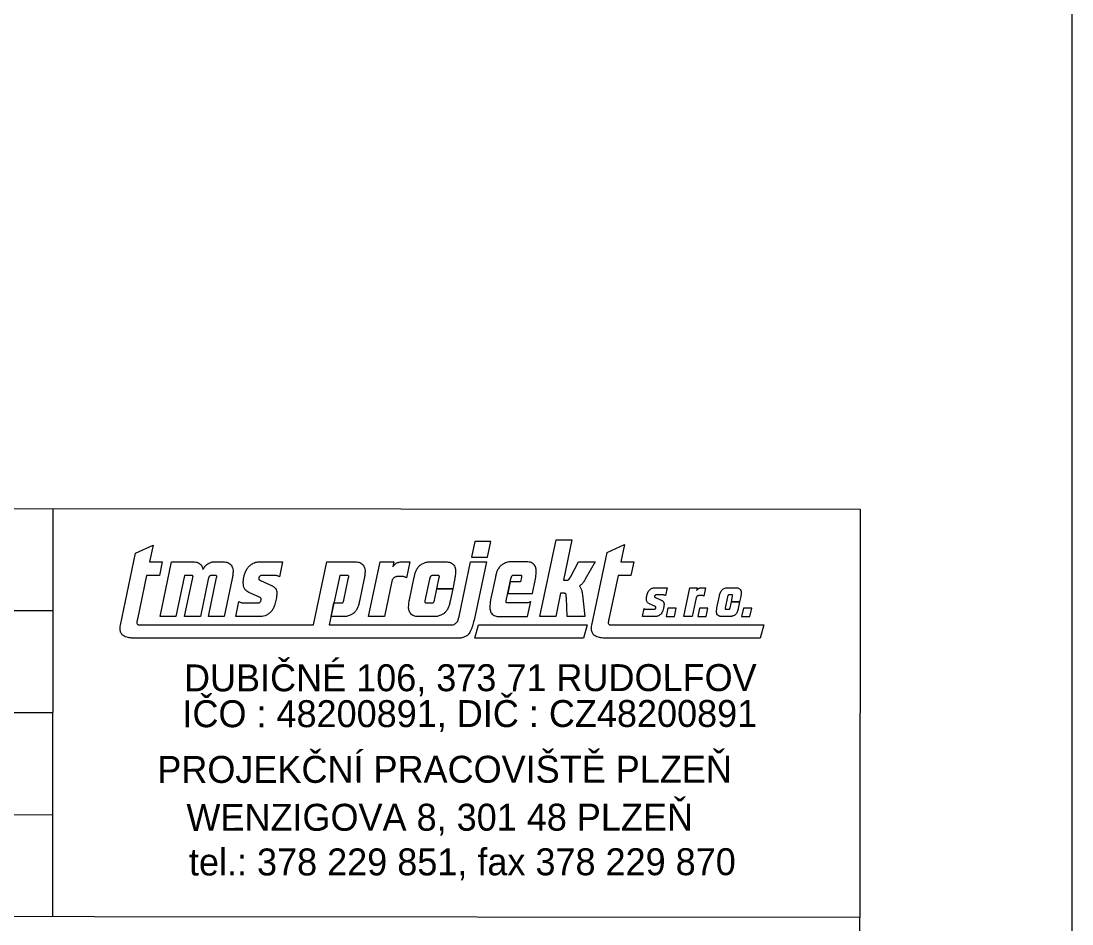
# Model space of a CAD drawing. Extents: x -712879 to -712656, y -1106692 to -1106395.
# Drawn here: x -712742.8 to -712668.6, y -1106637.9 to -1106574.3 of the extents above; entities that cross this region are included whole.
import ezdxf

# ---------------------------------------------------------------- set-up
doc = ezdxf.new("R2010")
doc.units = 0
doc.layers.add('Implicitní', color=7, linetype='Continuous')
doc.layers.add('Vrstva 63', color=7, linetype='Continuous')

msp = doc.modelspace()

# ---------------------------------------------------------------- linework, layer by layer
at = {"layer": 'Implicitní'}
for p, q in [((-712740.521, -1106608.636), (-712740.542, -1106637.436)), ((-712710.731, -1106610.956), (-712710.967, -1106612.074)), ((-712709.618, -1106610.956), (-712710.731, -1106610.956)), ((-712709.854, -1106612.074), (-712709.618, -1106610.956)), ((-712706.146, -1106616.265), (-712705.004, -1106610.846)), ((-712705.004, -1106610.846), (-712703.891, -1106610.846)), ((-712703.891, -1106610.846), (-712704.489, -1106613.684)), ((-712735.743, -1106616.859), (-712734.673, -1106611.779)), ((-712734.674, -1106611.779), (-712733.442, -1106611.218)), ((-712733.442, -1106611.218), (-712733.691, -1106612.402)), ((-712702.483, -1106616.859), (-712701.403, -1106611.73)), ((-712701.403, -1106611.73), (-712700.172, -1106611.169)), ((-712700.172, -1106611.169), (-712700.431, -1106612.402)), ((-712733.691, -1106612.402), (-712732.789, -1106612.402)), ((-712732.789, -1106612.402), (-712732.992, -1106613.367)), ((-712732.942, -1106616.265), (-712732.128, -1106612.402)), ((-712732.128, -1106612.402), (-712730.697, -1106612.402)), ((-712729.195, -1106612.402), (-712728.581, -1106612.402)), ((-712725.923, -1106612.402), (-712724.304, -1106612.402)), ((-712724.304, -1106612.402), (-712724.526, -1106613.455)), ((-712722.119, -1106616.854), (-712721.181, -1106612.402)), ((-712721.181, -1106612.402), (-712719.268, -1106612.402)), ((-712718.234, -1106616.265), (-712717.421, -1106612.402)), ((-712717.421, -1106612.402), (-712716.45, -1106612.402)), ((-712716.45, -1106612.402), (-712716.526, -1106612.764)), ((-712715.933, -1106612.402), (-712715.332, -1106612.402)), ((-712715.332, -1106612.402), (-712715.568, -1106613.522)), ((-712713.887, -1106612.402), (-712712.876, -1106612.402)), ((-712711.848, -1106616.257), (-712711.036, -1106612.402)), ((-712711.036, -1106612.402), (-712709.922, -1106612.402)), ((-712710.967, -1106612.074), (-712709.854, -1106612.074)), ((-712709.922, -1106612.402), (-712710.791, -1106616.526)), ((-712707.183, -1106612.402), (-712708.157, -1106612.402)), ((-712703.971, -1106613.445), (-712703.428, -1106612.402)), ((-712703.428, -1106612.402), (-712702.248, -1106612.402)), ((-712702.248, -1106612.402), (-712702.95, -1106613.632)), ((-712700.431, -1106612.402), (-712699.529, -1106612.402)), ((-712699.529, -1106612.402), (-712699.732, -1106613.367)), ((-712733.895, -1106613.367), (-712734.544, -1106616.451)), ((-712732.992, -1106613.367), (-712733.895, -1106613.367)), ((-712731.218, -1106613.367), (-712731.828, -1106616.265)), ((-712730.723, -1106613.367), (-712731.218, -1106613.367)), ((-712731.212, -1106616.265), (-712730.632, -1106613.51)), ((-712729.542, -1106613.622), (-712730.099, -1106616.265)), ((-712729.533, -1106616.265), (-712728.953, -1106613.512)), ((-712729.045, -1106613.367), (-712729.341, -1106613.367)), ((-712727.855, -1106613.581), (-712728.42, -1106616.265)), ((-712725.865, -1106613.723), (-712725.077, -1106614.076)), ((-712724.813, -1106613.367), (-712725.764, -1106613.367)), ((-712720.272, -1106613.367), (-712721.006, -1106616.854)), ((-712719.733, -1106613.367), (-712720.272, -1106613.367)), ((-712719.977, -1106615.098), (-712719.642, -1106613.509)), ((-712718.545, -1106613.584), (-712718.881, -1106615.181)), ((-712716.593, -1106613.757), (-712717.121, -1106616.265)), ((-712715.855, -1106613.435), (-712716.149, -1106613.435)), ((-712715.353, -1106615.079), (-712715.017, -1106613.483)), ((-712713.933, -1106613.622), (-712714.254, -1106615.149)), ((-712713.34, -1106613.367), (-712713.733, -1106613.367)), ((-712713.417, -1106614.304), (-712713.249, -1106613.509)), ((-712712.148, -1106613.587), (-712712.299, -1106614.304)), ((-712709.286, -1106613.485), (-712709.621, -1106615.077)), ((-712708.523, -1106615.148), (-712708.195, -1106613.588)), ((-712708.239, -1106613.799), (-712708.413, -1106614.622)), ((-712707.514, -1106613.799), (-712708.239, -1106613.799)), ((-712707.993, -1106613.331), (-712707.537, -1106613.331)), ((-712707.446, -1106613.474), (-712707.514, -1106613.799)), ((-712706.675, -1106614.622), (-712706.457, -1106613.588)), ((-712704.489, -1106613.684), (-712704.247, -1106613.684)), ((-712700.635, -1106613.367), (-712701.284, -1106616.451)), ((-712699.732, -1106613.367), (-712700.635, -1106613.367)), ((-712725.983, -1106614.867), (-712726.675, -1106614.558)), ((-712713.584, -1106615.098), (-712713.417, -1106614.304)), ((-712713.417, -1106614.304), (-712712.299, -1106614.304)), ((-712712.299, -1106614.304), (-712713.417, -1106614.304)), ((-712712.299, -1106614.304), (-712712.484, -1106615.182)), ((-712708.413, -1106614.622), (-712706.675, -1106614.622)), ((-712704.685, -1106614.615), (-712705.032, -1106616.265)), ((-712704.49, -1106614.615), (-712704.685, -1106614.615)), ((-712703.15, -1106614.717), (-712702.966, -1106616.265)), ((-712698.026, -1106614.229), (-712697.176, -1106614.229)), ((-712697.443, -1106614.736), (-712697.942, -1106614.736)), ((-712697.176, -1106614.229), (-712697.292, -1106614.782)), ((-712695.985, -1106616.258), (-712695.557, -1106614.229)), ((-712695.557, -1106614.229), (-712695.048, -1106614.229)), ((-712695.048, -1106614.229), (-712695.088, -1106614.42)), ((-712694.777, -1106614.229), (-712694.461, -1106614.229)), ((-712694.461, -1106614.229), (-712694.585, -1106614.817)), ((-712692.886, -1106614.229), (-712692.355, -1106614.229)), ((-712692.599, -1106614.736), (-712692.805, -1106614.736)), ((-712727.607, -1106616.265), (-712727.383, -1106615.204)), ((-712727.094, -1106615.291), (-712726.034, -1106615.291)), ((-712720.882, -1106616.265), (-712720.677, -1106615.291)), ((-712720.677, -1106615.291), (-712720.148, -1106615.291)), ((-712714.163, -1106615.291), (-712713.756, -1106615.291)), ((-712707.134, -1106615.291), (-712708.432, -1106615.291)), ((-712707.021, -1106616.265), (-712706.797, -1106615.202)), ((-712704.226, -1106616.265), (-712704.274, -1106614.939)), ((-712698.057, -1106615.524), (-712698.421, -1106615.361)), ((-712697.996, -1106614.923), (-712697.582, -1106615.108)), ((-712695.123, -1106614.941), (-712695.4, -1106616.258)), ((-712694.735, -1106614.772), (-712694.89, -1106614.772)), ((-712693.656, -1106615.635), (-712693.479, -1106614.797)), ((-712692.91, -1106614.87), (-712693.079, -1106615.671)), ((-712692.727, -1106615.645), (-712692.639, -1106615.228)), ((-712692.639, -1106615.228), (-712692.551, -1106614.811)), ((-712692.639, -1106615.228), (-712692.052, -1106615.228)), ((-712692.052, -1106615.228), (-712692.639, -1106615.228)), ((-712692.052, -1106615.228), (-712692.149, -1106615.689)), ((-712691.973, -1106614.851), (-712692.052, -1106615.228)), ((-712845.565, -1106615.757), (-712740.526, -1106615.835)), ((-712698.91, -1106616.258), (-712698.793, -1106615.7)), ((-712698.641, -1106615.746), (-712698.084, -1106615.746)), ((-712697.114, -1106615.67), (-712697.238, -1106616.258)), ((-712696.529, -1106615.67), (-712697.114, -1106615.67)), ((-712696.653, -1106616.258), (-712696.529, -1106615.67)), ((-712694.878, -1106615.67), (-712695.002, -1106616.258)), ((-712694.294, -1106615.67), (-712694.878, -1106615.67)), ((-712694.417, -1106616.258), (-712694.294, -1106615.67)), ((-712693.031, -1106615.746), (-712692.817, -1106615.746)), ((-712691.789, -1106615.67), (-712691.913, -1106616.258)), ((-712691.205, -1106615.67), (-712691.789, -1106615.67)), ((-712691.328, -1106616.258), (-712691.205, -1106615.67)), ((-712734.359, -1106616.854), (-712722.119, -1106616.854)), ((-712731.828, -1106616.265), (-712732.942, -1106616.265)), ((-712730.099, -1106616.265), (-712731.212, -1106616.265)), ((-712728.42, -1106616.265), (-712729.533, -1106616.265)), ((-712725.97, -1106616.265), (-712727.607, -1106616.265)), ((-712721.006, -1106616.854), (-712712.459, -1106616.854)), ((-712720.012, -1106616.265), (-712720.882, -1106616.265)), ((-712717.121, -1106616.265), (-712718.234, -1106616.265)), ((-712713.614, -1106616.265), (-712714.628, -1106616.265)), ((-712710.738, -1106617.782), (-712710.481, -1106616.854)), ((-712710.481, -1106616.854), (-712702.82, -1106616.854)), ((-712708.898, -1106616.265), (-712707.021, -1106616.265)), ((-712705.032, -1106616.265), (-712706.146, -1106616.265)), ((-712702.966, -1106616.265), (-712704.226, -1106616.265)), ((-712702.82, -1106616.854), (-712703.076, -1106617.782)), ((-712701.099, -1106616.854), (-712690.345, -1106616.854)), ((-712698.051, -1106616.258), (-712698.91, -1106616.258)), ((-712697.238, -1106616.258), (-712696.653, -1106616.258)), ((-712695.4, -1106616.258), (-712695.985, -1106616.258)), ((-712695.002, -1106616.258), (-712694.417, -1106616.258)), ((-712692.743, -1106616.258), (-712693.275, -1106616.258)), ((-712691.913, -1106616.258), (-712691.328, -1106616.258)), ((-712690.345, -1106616.854), (-712690.602, -1106617.782)), ((-712711.906, -1106617.782), (-712734.869, -1106617.782)), ((-712703.076, -1106617.782), (-712710.738, -1106617.782)), ((-712690.602, -1106617.782), (-712701.609, -1106617.782)), ((-712845.571, -1106622.957), (-712740.532, -1106623.035)), ((-712845.576, -1106630.157), (-712740.537, -1106630.235))]:
    msp.add_line(p, q, dxfattribs=at)
for points in [[(-712845.56, -1106608.557), (-712683.555, -1106608.677), (-712683.576, -1106637.478), (-712845.581, -1106637.358)], [(-712845.585, -1106644.557), (-712683.582, -1106644.677), (-712683.576, -1106637.478), (-712845.579, -1106637.358)]]:
    msp.add_lwpolyline(points, close=True, dxfattribs=at)
for points in [[(-712730.697, -1106612.401), (-712730.605, -1106612.402), (-712730.429, -1106612.415), (-712730.286, -1106612.447), (-712730.142, -1106612.53), (-712729.968, -1106612.761), (-712729.938, -1106612.872), (-712729.925, -1106612.921), (-712729.919, -1106612.949)], [(-712729.919, -1106612.949), (-712729.815, -1106612.775), (-712729.707, -1106612.647), (-712729.571, -1106612.536), (-712729.48, -1106612.483), (-712729.373, -1106612.44), (-712729.29, -1106612.419), (-712729.195, -1106612.402)], [(-712728.581, -1106612.401), (-712728.489, -1106612.402), (-712728.313, -1106612.415), (-712728.169, -1106612.447), (-712728.026, -1106612.53), (-712727.852, -1106612.761), (-712727.822, -1106612.872), (-712727.809, -1106612.921), (-712727.814, -1106613.276), (-712727.831, -1106613.435), (-712727.855, -1106613.581)], [(-712726.675, -1106614.558), (-712726.819, -1106614.464), (-712726.93, -1106614.369), (-712727.031, -1106614.195), (-712727.068, -1106613.991), (-712727.072, -1106613.793), (-712727.037, -1106613.508), (-712726.985, -1106613.296), (-712726.886, -1106613.037), (-712726.758, -1106612.815), (-712726.593, -1106612.649), (-712726.376, -1106612.499), (-712726.207, -1106612.433), (-712726.045, -1106612.404), (-712725.923, -1106612.402)], [(-712719.268, -1106612.401), (-712719.176, -1106612.402), (-712718.999, -1106612.415), (-712718.856, -1106612.447), (-712718.712, -1106612.53), (-712718.538, -1106612.761), (-712718.508, -1106612.872), (-712718.496, -1106612.921), (-712718.5, -1106613.276), (-712718.518, -1106613.435), (-712718.545, -1106613.584)], [(-712716.526, -1106612.764), (-712716.455, -1106612.667), (-712716.399, -1106612.603), (-712716.313, -1106612.528), (-712716.238, -1106612.482), (-712716.133, -1106612.436), (-712716.043, -1106612.413), (-712715.933, -1106612.402)], [(-712715.017, -1106613.483), (-712714.966, -1106613.256), (-712714.885, -1106613.026), (-712714.758, -1106612.809), (-712714.631, -1106612.666), (-712714.451, -1106612.547), (-712714.299, -1106612.473), (-712714.168, -1106612.431), (-712714.048, -1106612.406), (-712713.887, -1106612.402)], [(-712712.876, -1106612.401), (-712712.784, -1106612.402), (-712712.607, -1106612.415), (-712712.464, -1106612.447), (-712712.32, -1106612.53), (-712712.146, -1106612.761), (-712712.116, -1106612.872), (-712712.104, -1106612.921), (-712712.108, -1106613.276), (-712712.126, -1106613.435), (-712712.148, -1106613.587)], [(-712708.157, -1106612.402), (-712708.317, -1106612.406), (-712708.438, -1106612.431), (-712708.569, -1106612.473), (-712708.721, -1106612.547), (-712708.901, -1106612.666), (-712709.028, -1106612.809), (-712709.154, -1106613.026), (-712709.236, -1106613.256), (-712709.286, -1106613.485)], [(-712706.457, -1106613.588), (-712706.433, -1106613.435), (-712706.416, -1106613.276), (-712706.411, -1106612.921), (-712706.424, -1106612.872), (-712706.454, -1106612.761), (-712706.628, -1106612.53), (-712706.771, -1106612.447), (-712706.915, -1106612.415), (-712707.091, -1106612.402), (-712707.183, -1106612.401)], [(-712730.632, -1106613.51), (-712730.626, -1106613.476), (-712730.621, -1106613.438), (-712730.627, -1106613.403), (-712730.645, -1106613.38), (-712730.678, -1106613.369), (-712730.723, -1106613.367)], [(-712729.341, -1106613.367), (-712729.37, -1106613.369), (-712729.403, -1106613.377), (-712729.437, -1106613.398), (-712729.48, -1106613.444), (-712729.503, -1106613.491), (-712729.542, -1106613.622)], [(-712728.953, -1106613.512), (-712728.947, -1106613.476), (-712728.942, -1106613.438), (-712728.949, -1106613.403), (-712728.967, -1106613.38), (-712729, -1106613.369), (-712729.045, -1106613.367)], [(-712725.764, -1106613.367), (-712725.84, -1106613.375), (-712725.881, -1106613.395), (-712725.926, -1106613.431), (-712725.957, -1106613.485), (-712725.975, -1106613.548), (-712725.977, -1106613.615), (-712725.958, -1106613.661), (-712725.914, -1106613.693), (-712725.865, -1106613.723)], [(-712724.526, -1106613.455), (-712724.589, -1106613.419), (-712724.654, -1106613.391), (-712724.693, -1106613.379), (-712724.763, -1106613.369), (-712724.813, -1106613.367)], [(-712719.642, -1106613.509), (-712719.635, -1106613.476), (-712719.63, -1106613.438), (-712719.637, -1106613.403), (-712719.655, -1106613.38), (-712719.688, -1106613.369), (-712719.733, -1106613.367)], [(-712716.149, -1106613.435), (-712716.22, -1106613.441), (-712716.289, -1106613.454), (-712716.372, -1106613.487), (-712716.444, -1106613.527), (-712716.499, -1106613.577), (-712716.56, -1106613.662), (-712716.593, -1106613.757)], [(-712715.568, -1106613.522), (-712715.632, -1106613.486), (-712715.697, -1106613.459), (-712715.736, -1106613.447), (-712715.788, -1106613.438), (-712715.855, -1106613.435)], [(-712713.733, -1106613.367), (-712713.762, -1106613.369), (-712713.795, -1106613.377), (-712713.829, -1106613.398), (-712713.872, -1106613.444), (-712713.895, -1106613.491), (-712713.934, -1106613.621)], [(-712713.249, -1106613.509), (-712713.243, -1106613.476), (-712713.238, -1106613.438), (-712713.244, -1106613.403), (-712713.262, -1106613.38), (-712713.296, -1106613.369), (-712713.34, -1106613.367)], [(-712708.195, -1106613.588), (-712708.155, -1106613.454), (-712708.132, -1106613.408), (-712708.089, -1106613.361), (-712708.055, -1106613.34), (-712708.021, -1106613.332), (-712707.993, -1106613.331)], [(-712707.537, -1106613.331), (-712707.492, -1106613.333), (-712707.459, -1106613.343), (-712707.441, -1106613.366), (-712707.434, -1106613.401), (-712707.439, -1106613.44), (-712707.446, -1106613.474)], [(-712704.247, -1106613.684), (-712704.177, -1106613.682), (-712704.15, -1106613.673), (-712704.111, -1106613.647), (-712704.079, -1106613.611), (-712703.986, -1106613.475), (-712703.971, -1106613.445)], [(-712702.95, -1106613.632), (-712703.04, -1106613.79), (-712703.112, -1106613.89), (-712703.187, -1106613.969), (-712703.252, -1106614.029), (-712703.356, -1106614.107)], [(-712725.077, -1106614.076), (-712725.024, -1106614.101), (-712724.919, -1106614.171), (-712724.84, -1106614.241), (-712724.764, -1106614.34), (-712724.729, -1106614.427), (-712724.707, -1106614.662), (-712724.739, -1106614.927), (-712724.824, -1106615.321), (-712724.889, -1106615.529), (-712725.006, -1106615.771), (-712725.184, -1106615.982), (-712725.355, -1106616.113), (-712725.539, -1106616.204), (-712725.743, -1106616.254), (-712725.97, -1106616.265)], [(-712704.274, -1106614.939), (-712704.285, -1106614.791), (-712704.299, -1106614.688), (-712704.33, -1106614.651), (-712704.374, -1106614.628), (-712704.412, -1106614.618), (-712704.49, -1106614.615)], [(-712703.356, -1106614.107), (-712703.306, -1106614.188), (-712703.259, -1106614.263), (-712703.225, -1106614.33), (-712703.194, -1106614.433), (-712703.167, -1106614.572), (-712703.15, -1106614.717)], [(-712698.421, -1106615.361), (-712698.497, -1106615.312), (-712698.555, -1106615.262), (-712698.608, -1106615.171), (-712698.627, -1106615.064), (-712698.63, -1106614.96), (-712698.611, -1106614.81), (-712698.584, -1106614.699), (-712698.532, -1106614.563), (-712698.464, -1106614.446), (-712698.378, -1106614.359), (-712698.264, -1106614.28), (-712698.175, -1106614.246), (-712698.09, -1106614.23), (-712698.026, -1106614.229)], [(-712697.942, -1106614.736), (-712697.982, -1106614.74), (-712698.004, -1106614.751), (-712698.028, -1106614.77), (-712698.044, -1106614.798), (-712698.054, -1106614.831), (-712698.055, -1106614.866), (-712698.044, -1106614.89), (-712698.021, -1106614.907), (-712697.996, -1106614.923)], [(-712697.292, -1106614.782), (-712697.326, -1106614.763), (-712697.36, -1106614.749), (-712697.381, -1106614.742), (-712697.417, -1106614.737), (-712697.443, -1106614.736)], [(-712695.088, -1106614.42), (-712695.051, -1106614.368), (-712695.021, -1106614.335), (-712694.976, -1106614.296), (-712694.936, -1106614.271), (-712694.881, -1106614.247), (-712694.834, -1106614.235), (-712694.777, -1106614.229)], [(-712693.479, -1106614.797), (-712693.452, -1106614.678), (-712693.41, -1106614.557), (-712693.343, -1106614.443), (-712693.277, -1106614.368), (-712693.182, -1106614.306), (-712693.102, -1106614.267), (-712693.034, -1106614.244), (-712692.97, -1106614.231), (-712692.886, -1106614.229)], [(-712692.805, -1106614.736), (-712692.82, -1106614.737), (-712692.838, -1106614.741), (-712692.855, -1106614.752), (-712692.878, -1106614.777), (-712692.89, -1106614.801), (-712692.911, -1106614.87)], [(-712692.551, -1106614.811), (-712692.548, -1106614.793), (-712692.545, -1106614.773), (-712692.549, -1106614.755), (-712692.558, -1106614.743), (-712692.576, -1106614.737), (-712692.599, -1106614.736)], [(-712692.355, -1106614.229), (-712692.307, -1106614.23), (-712692.214, -1106614.236), (-712692.139, -1106614.253), (-712692.064, -1106614.297), (-712691.972, -1106614.418), (-712691.956, -1106614.476), (-712691.95, -1106614.502), (-712691.952, -1106614.688), (-712691.961, -1106614.772), (-712691.973, -1106614.851)], [(-712727.383, -1106615.204), (-712727.32, -1106615.24), (-712727.255, -1106615.268), (-712727.215, -1106615.279), (-712727.146, -1106615.29), (-712727.094, -1106615.291)], [(-712726.034, -1106615.291), (-712725.96, -1106615.288), (-712725.916, -1106615.262), (-712725.862, -1106615.203), (-712725.832, -1106615.129), (-712725.82, -1106615.036), (-712725.832, -1106614.979), (-712725.861, -1106614.94), (-712725.926, -1106614.901), (-712725.983, -1106614.867)], [(-712720.148, -1106615.291), (-712720.081, -1106615.289), (-712720.035, -1106615.263), (-712720.009, -1106615.208), (-712719.994, -1106615.16), (-712719.977, -1106615.098)], [(-712718.881, -1106615.181), (-712718.933, -1106615.411), (-712719.014, -1106615.64), (-712719.141, -1106615.858), (-712719.267, -1106616.001), (-712719.448, -1106616.119), (-712719.6, -1106616.194), (-712719.731, -1106616.236), (-712719.851, -1106616.261), (-712720.012, -1106616.265)], [(-712714.628, -1106616.265), (-712714.72, -1106616.264), (-712714.896, -1106616.251), (-712715.04, -1106616.22), (-712715.183, -1106616.137), (-712715.357, -1106615.906), (-712715.387, -1106615.794), (-712715.4, -1106615.746), (-712715.395, -1106615.391), (-712715.378, -1106615.232), (-712715.353, -1106615.079)], [(-712714.254, -1106615.149), (-712714.261, -1106615.183), (-712714.266, -1106615.221), (-712714.259, -1106615.256), (-712714.241, -1106615.279), (-712714.208, -1106615.289), (-712714.163, -1106615.291)], [(-712713.756, -1106615.291), (-712713.688, -1106615.289), (-712713.643, -1106615.263), (-712713.616, -1106615.208), (-712713.602, -1106615.16), (-712713.584, -1106615.098)], [(-712712.484, -1106615.182), (-712712.536, -1106615.411), (-712712.617, -1106615.64), (-712712.743, -1106615.858), (-712712.87, -1106616.001), (-712713.05, -1106616.119), (-712713.203, -1106616.194), (-712713.333, -1106616.236), (-712713.454, -1106616.261), (-712713.614, -1106616.265)], [(-712709.621, -1106615.077), (-712709.647, -1106615.232), (-712709.665, -1106615.391), (-712709.67, -1106615.746), (-712709.657, -1106615.794), (-712709.627, -1106615.906), (-712709.453, -1106616.137), (-712709.31, -1106616.22), (-712709.166, -1106616.251), (-712708.99, -1106616.264), (-712708.898, -1106616.265)], [(-712708.432, -1106615.291), (-712708.477, -1106615.289), (-712708.51, -1106615.279), (-712708.528, -1106615.256), (-712708.535, -1106615.221), (-712708.53, -1106615.183), (-712708.523, -1106615.148)], [(-712706.798, -1106615.202), (-712706.851, -1106615.233), (-712706.922, -1106615.268), (-712707.023, -1106615.291), (-712707.134, -1106615.291)], [(-712697.582, -1106615.108), (-712697.554, -1106615.121), (-712697.499, -1106615.158), (-712697.457, -1106615.195), (-712697.417, -1106615.247), (-712697.399, -1106615.292), (-712697.388, -1106615.416), (-712697.405, -1106615.555), (-712697.449, -1106615.762), (-712697.483, -1106615.871), (-712697.545, -1106615.998), (-712697.638, -1106616.109), (-712697.728, -1106616.178), (-712697.824, -1106616.225), (-712697.931, -1106616.251), (-712698.051, -1106616.258)], [(-712694.89, -1106614.772), (-712694.927, -1106614.775), (-712694.963, -1106614.782), (-712695.007, -1106614.799), (-712695.044, -1106614.82), (-712695.074, -1106614.846), (-712695.106, -1106614.891), (-712695.123, -1106614.941)], [(-712694.585, -1106614.817), (-712694.618, -1106614.799), (-712694.652, -1106614.784), (-712694.673, -1106614.778), (-712694.7, -1106614.774), (-712694.735, -1106614.772)], [(-712698.793, -1106615.7), (-712698.759, -1106615.719), (-712698.725, -1106615.734), (-712698.705, -1106615.74), (-712698.668, -1106615.745), (-712698.641, -1106615.746)], [(-712698.084, -1106615.746), (-712698.045, -1106615.744), (-712698.022, -1106615.731), (-712697.994, -1106615.7), (-712697.978, -1106615.661), (-712697.972, -1106615.612), (-712697.978, -1106615.582), (-712697.993, -1106615.562), (-712698.028, -1106615.541), (-712698.057, -1106615.524)], [(-712693.275, -1106616.258), (-712693.323, -1106616.257), (-712693.416, -1106616.25), (-712693.491, -1106616.234), (-712693.567, -1106616.19), (-712693.658, -1106616.069), (-712693.674, -1106616.01), (-712693.68, -1106615.985), (-712693.678, -1106615.798), (-712693.669, -1106615.715), (-712693.656, -1106615.635)], [(-712693.079, -1106615.671), (-712693.082, -1106615.689), (-712693.085, -1106615.709), (-712693.081, -1106615.728), (-712693.072, -1106615.74), (-712693.054, -1106615.745), (-712693.031, -1106615.746)], [(-712692.817, -1106615.746), (-712692.782, -1106615.745), (-712692.758, -1106615.731), (-712692.744, -1106615.703), (-712692.736, -1106615.677), (-712692.727, -1106615.645)], [(-712692.149, -1106615.689), (-712692.177, -1106615.809), (-712692.219, -1106615.929), (-712692.286, -1106616.044), (-712692.352, -1106616.119), (-712692.447, -1106616.181), (-712692.527, -1106616.22), (-712692.595, -1106616.242), (-712692.659, -1106616.255), (-712692.743, -1106616.258)], [(-712734.869, -1106617.782), (-712735.203, -1106617.742), (-712735.387, -1106617.686), (-712735.543, -1106617.605), (-712735.678, -1106617.465), (-712735.757, -1106617.237), (-712735.767, -1106617.074), (-712735.743, -1106616.859)], [(-712734.544, -1106616.451), (-712734.567, -1106616.56), (-712734.581, -1106616.668), (-712734.571, -1106616.766), (-712734.519, -1106616.826), (-712734.448, -1106616.847), (-712734.359, -1106616.854)], [(-712712.459, -1106616.854), (-712712.338, -1106616.85), (-712712.202, -1106616.813), (-712712.1, -1106616.751), (-712712.004, -1106616.665), (-712711.909, -1106616.483), (-712711.879, -1106616.377), (-712711.848, -1106616.257)], [(-712710.791, -1106616.526), (-712710.909, -1106616.932), (-712710.98, -1106617.136), (-712711.059, -1106617.305), (-712711.144, -1106617.451), (-712711.304, -1106617.613), (-712711.524, -1106617.72), (-712711.74, -1106617.778), (-712711.906, -1106617.782)], [(-712701.609, -1106617.782), (-712701.943, -1106617.742), (-712702.127, -1106617.686), (-712702.283, -1106617.605), (-712702.418, -1106617.465), (-712702.497, -1106617.237), (-712702.507, -1106617.074), (-712702.483, -1106616.859)], [(-712701.284, -1106616.451), (-712701.307, -1106616.56), (-712701.321, -1106616.668), (-712701.311, -1106616.766), (-712701.259, -1106616.826), (-712701.188, -1106616.847), (-712701.099, -1106616.854)]]:
    msp.add_spline(points, degree=3, dxfattribs=at)
at = {"layer": 'Vrstva 63'}
msp.add_lwpolyline([(-712878.605, -1106394.843), (-712668.605, -1106394.843), (-712668.605, -1106691.843), (-712878.605, -1106691.843)], close=True, dxfattribs=at)

# ---------------------------------------------------------------- texts
at = {"layer": 'Implicitní'}
for s, p in [('DUBIČNÉ 106, 373 71 RUDOLFOV', (-712731.256, -1106621.537)), ('IČO : 48200891, DIČ : CZ48200891', (-712731.367, -1106624.067)), ('PROJEKČNÍ PRACOVIŠTĚ PLZEŇ', (-712733.138, -1106627.996)), ('WENZIGOVA 8, 301 48 PLZEŇ', (-712731.086, -1106631.376)), ('tel.: 378 229 851, fax 378 229 870', (-712730.908, -1106634.525))]:
    msp.add_text(s, height=1.9008, rotation=0.03338, dxfattribs=at).set_placement(p)

doc.saveas('drawing.dxf')
